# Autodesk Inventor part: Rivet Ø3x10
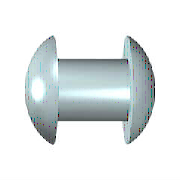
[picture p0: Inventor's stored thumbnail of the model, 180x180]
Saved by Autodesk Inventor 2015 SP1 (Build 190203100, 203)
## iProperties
IsCustomPart: 1
Created: 2011-02
Part Number: Rivet Ø3x10
Material: Steel, Mild
Description: ISO/R 1051 - 3 x 10
Document SubType Name: Modeling
Standard: ISO 1051
Designer: Guilherme Augusto Franco de Souza
Standard Revision: First edition 1999-12-01
Standards Organization: ISO
Language: en-US
Size Designation: 3 x 10
Categories: <MemberInstance><Categories><Category DisplayName="Fasteners" InternalName="e4da775c-781d-43d5-af7c-5136215cf5a6" Mnemonic="FSTN"><Category DisplayName="Rivets"
Density: 1 g/cm^3
Appearance: Steel
Author: Guilherme Augusto Franco de Souza
Revision Number: 00
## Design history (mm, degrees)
sketch "Sketch"
  geometry: L1 (0, 1.5)-(5.742, 1.5); L2 (5.742, 1.5)-(5.742, 2.6); L3 (0, 1.5)-(0, 2.6); L4 (-1.8, 0)-(7.542, 0); L5 (-3.837, 0)-(7.579, 0) reference; L6 (0, -0.576)-(0, 3.457) reference; A1 r 2.778 centre (0.978, 0) between (0, 2.6) and (-1.8, 0); A2 r 2.778 centre (4.764, 0) between (7.542, 0) and (5.742, 2.6)
  constraints: 8 end point, 5 point on circle, 4 point on line, 2 centre point, 2 collinear, 2 perpendicular, 1 horizontal, 1 parallel
  dimensions: "d0" = 3 diameter of L1 L4 (= NND1); "d1" = 5.742 distance of L1.start L1.end (computed from KLG); "d2" = 5.2 diameter of L3.end L4 (= KOD); "d3" = 1.8 horizontal distance of L4.start L3.end (= KOH); "d4" = 5.2 diameter of L2.end L4 (= KOD1); "d5" = 1.8 horizontal distance of L4.end L2.end (= KOH1)
revolve "Body" sketch "Sketch" stored, may be unused: angle "d11" = 90 deg
body "Solid1"
other parameters: "KOH" = 1.8 [user parameter; used in 2 equation terms], "KOH1" = 1.8 (= KOH) [user parameter; used in 1 equation term], "KOD" = 5.2 [user parameter; used in 2 equation terms], "KOD1" = 5.2 (= KOD) [user parameter; used in 1 equation term], "NND1" = 3 (= NND) [user parameter; used in 1 equation term], "KLG" = 5.741 [user parameter; used in 1 equation term], "d7" = 0, "d15" = 0, "d16" = 0, "KLGMIN" = 0.001 [user parameter], "NND" = 3 [user parameter; used in 1 equation term], "KLGMAX" = 5.5 [user parameter]
